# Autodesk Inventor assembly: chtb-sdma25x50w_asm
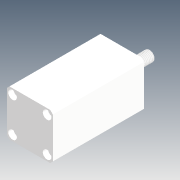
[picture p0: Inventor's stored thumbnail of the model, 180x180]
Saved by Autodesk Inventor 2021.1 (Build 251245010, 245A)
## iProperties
Company: Microsoft
Created: 2018-05
Part Number: chtb-sdma25x50w_asm
Description: STEP AP214
Document SubType Name: Assembly
Designer: user
Title: chtb-sdma25x50w_asm.STEP
Author: Windows
Revision Number: ÈÎºÎ
Sending System: SolidWorks 2015
Preprocessor: SwSTEP 2.0
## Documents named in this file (4)
- D:\Vault_2016\Projekty\Clamptek\Hydraulic\CHTB\CHTB-25\Inventor\chtb-sdma25x50w\chtb-sdma25x50w_asm.iam
- D:\Vault_2016\Projekty\Clamptek\Hydraulic\CHTB\CHTB-25\Inventor\chtb-sdma25x50w\CHTB-25QG.ipt
- D:\Vault_2016\Projekty\Clamptek\Hydraulic\CHTB\CHTB-25\Inventor\chtb-sdma25x50w\CHTB-SDMA25X50NBT.ipt
- D:\Vault_2016\Projekty\Clamptek\Hydraulic\CHTB\CHTB-25\Inventor\chtb-sdma25x50w\CHTB-SDMA25X50WHSG.ipt
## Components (3 placed, 3 different names)
1. CHTB-25QG_1
2. CHTB-SDMA25X50NBT_2
3. CHTB-SDMA25X50WHSG_3
